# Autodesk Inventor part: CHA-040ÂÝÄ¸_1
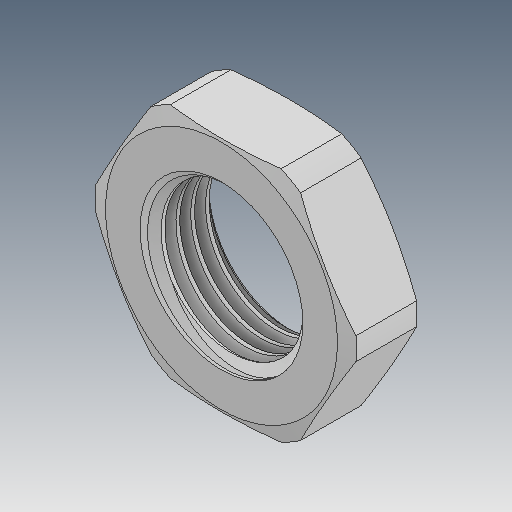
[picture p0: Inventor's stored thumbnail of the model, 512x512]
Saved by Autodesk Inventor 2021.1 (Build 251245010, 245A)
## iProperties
Created: 2019-12
Part Number: CHA-040ÂÝÄ¸_1
Material: Ogólny
Document SubType Name: Modeling
Designer: user
Density: 1 g/cm^3
Appearance: Domyślna
Author: user
Revision Number: ÈÎºÎ
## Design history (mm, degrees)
feature "ÊäÈë1"
node "Bryła1"
